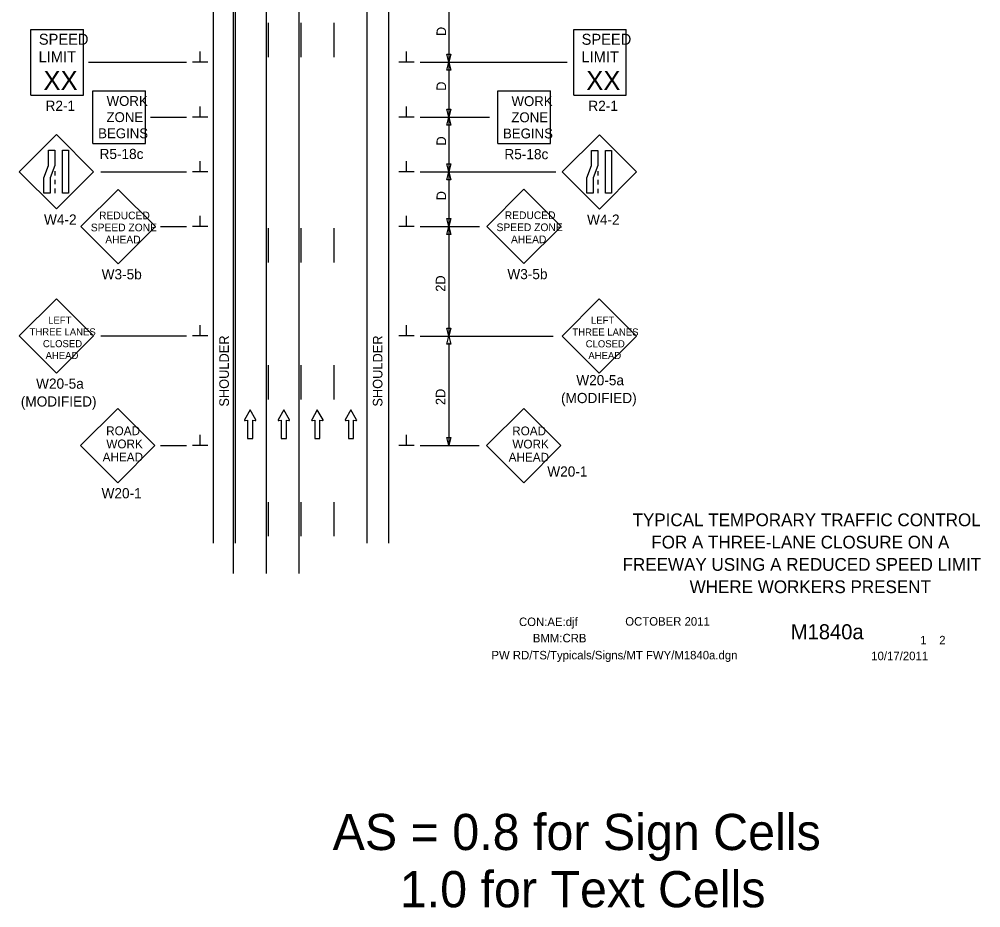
# Model space of a CAD drawing. Extents: x 16726 to 18475, y 5752 to 6929.
# Drawn here: x 16726 to 17428, y 5752 to 6401 of the extents above; entities that cross this region are included whole.
import ezdxf

# ---------------------------------------------------------------- set-up
doc = ezdxf.new("R2010")
doc.units = 0
for name, color, linetype in [('ALI_LEGAL_EX', 7, 'Continuous'), ('BORDER', 7, 'Continuous'), ('BORDER_SIGNAL_WO', 7, 'Continuous'), ('MT_SCRATCH_LEVEL_E', 7, 'Continuous'), ('PAVT_EDGE_EX', 7, 'Continuous'), ('TRAFFIC_SIGNS_PR', 7, 'Continuous'), ('TYPICAL_TEXT_DIMEN_PR', 7, 'Continuous')]:
    doc.layers.add(name, color=color, linetype=linetype)

msp = doc.modelspace()

# ---------------------------------------------------------------- linework, layer by layer
at = {"layer": 'ALI_LEGAL_EX'}
for p, q in [((16881.97, 6876.43), (16881.97, 5996.39)), ((16905.97, 6876.43), (16905.97, 5996.39)), ((16929.97, 6876.43), (16929.97, 5996.39))]:
    msp.add_line(p, q, dxfattribs=at)
for points in [[(16907.45, 6398.64), (16907.45, 6373.64)], [(16931.45, 6398.64), (16931.45, 6373.64)], [(16955.45, 6398.64), (16955.45, 6373.64)], [(16907.45, 6248.64), (16907.45, 6223.64)], [(16931.45, 6248.64), (16931.45, 6223.64)], [(16955.45, 6248.64), (16955.45, 6223.64)], [(16907.45, 6148.64), (16907.45, 6123.64)], [(16931.45, 6148.64), (16931.45, 6123.64)], [(16955.45, 6148.64), (16955.45, 6123.64)], [(16907.45, 6048.64), (16907.45, 6023.64)], [(16931.45, 6048.64), (16931.45, 6023.64)], [(16955.45, 6048.64), (16955.45, 6023.64)]]:
    msp.add_lwpolyline(points, dxfattribs=at)
at = {"layer": 'MT_SCRATCH_LEVEL_E'}
for p, q in [((16894.36, 6116.04), (16890.25, 6108.8)), ((16898.5, 6108.8), (16894.36, 6116.04)), ((16918.89, 6116.04), (16914.77, 6108.8)), ((16923.03, 6108.8), (16918.89, 6116.04)), ((16943.41, 6116.04), (16939.3, 6108.8)), ((16947.56, 6108.8), (16943.41, 6116.04)), ((16967.97, 6116.04), (16963.86, 6108.8)), ((16972.12, 6108.8), (16967.97, 6116.04)), ((16890.73, 6108.12), (16892.5, 6108.43)), ((16892.5, 6108.43), (16892.5, 6095.18)), ((16896.25, 6095.18), (16896.25, 6108.43)), ((16896.25, 6108.43), (16898.02, 6108.12)), ((16915.26, 6108.12), (16917.03, 6108.43)), ((16917.03, 6108.43), (16917.03, 6095.18)), ((16920.78, 6095.18), (16920.78, 6108.43)), ((16920.78, 6108.43), (16922.55, 6108.12)), ((16939.79, 6108.12), (16941.56, 6108.43)), ((16941.56, 6108.43), (16941.56, 6095.18)), ((16945.3, 6095.18), (16945.3, 6108.43)), ((16945.3, 6108.43), (16947.08, 6108.12)), ((16964.34, 6108.12), (16966.12, 6108.43)), ((16966.12, 6108.43), (16966.12, 6095.18)), ((16969.86, 6095.18), (16969.86, 6108.43)), ((16969.86, 6108.43), (16971.64, 6108.12)), ((16892.5, 6095.18), (16896.25, 6095.18)), ((16917.03, 6095.18), (16920.78, 6095.18)), ((16941.56, 6095.18), (16945.3, 6095.18)), ((16966.12, 6095.18), (16969.86, 6095.18))]:
    msp.add_line(p, q, dxfattribs=at)
for centre, start, end in [((16890.65, 6108.58), 150.42484, 279.96381), ((16898.09, 6108.58), 260.03619, 29.77312), ((16915.18, 6108.58), 150.42484, 279.96381), ((16922.62, 6108.58), 260.03619, 29.77312), ((16939.71, 6108.58), 150.42484, 279.96381), ((16947.15, 6108.58), 260.03619, 29.77312), ((16964.27, 6108.58), 150.42484, 279.96381), ((16971.71, 6108.58), 260.03619, 29.77312)]:
    msp.add_arc(centre, 0.463, start, end, dxfattribs=at)
at = {"layer": 'PAVT_EDGE_EX'}
for p, q in [((16867.45, 6928.88), (16867.45, 6018.6)), ((16883.45, 6928.88), (16883.45, 6018.6)), ((16979.45, 6928.88), (16979.45, 6018.6)), ((16995.45, 6928.88), (16995.45, 6018.6))]:
    msp.add_line(p, q, dxfattribs=at)
at = {"layer": 'TRAFFIC_SIGNS_PR'}
for p, q in [((16734.26, 6393.85), (16772.66, 6393.85)), ((16734.26, 6345.85), (16734.26, 6393.85)), ((16772.66, 6345.85), (16772.66, 6393.85)), ((17130.66, 6393.81), (17169.06, 6393.81)), ((17130.66, 6345.81), (17130.66, 6393.81)), ((17169.06, 6345.81), (17169.06, 6393.81)), ((16779.55, 6310.65), (16779.55, 6349.05)), ((16779.55, 6349.05), (16817.95, 6349.05)), ((16817.95, 6310.65), (16817.95, 6349.05)), ((17075.22, 6310.52), (17075.22, 6348.92)), ((17075.22, 6348.92), (17113.62, 6348.92)), ((17113.62, 6310.52), (17113.62, 6348.92)), ((16734.26, 6345.85), (16772.66, 6345.85)), ((17130.66, 6345.81), (17169.06, 6345.81)), ((16752.87, 6317.04), (16725.71, 6289.89)), ((16780.02, 6289.89), (16752.87, 6317.04)), ((17149.41, 6316.97), (17122.26, 6289.82)), ((17176.56, 6289.82), (17149.41, 6316.97)), ((16779.55, 6310.65), (16817.95, 6310.65)), ((17075.22, 6310.52), (17113.62, 6310.52)), ((16725.71, 6289.89), (16752.87, 6262.74)), ((16751.62, 6290.38), (16751.62, 6287.18)), ((16752.87, 6262.74), (16780.02, 6289.89)), ((17122.26, 6289.82), (17149.41, 6262.67)), ((17148.16, 6290.31), (17148.16, 6287.11)), ((17149.41, 6262.67), (17176.56, 6289.82)), ((16751.62, 6283.98), (16751.62, 6280.78)), ((17148.16, 6283.91), (17148.16, 6280.71)), ((16751.62, 6277.58), (16751.62, 6274.38)), ((16797.96, 6277.05), (16770.81, 6249.9)), ((16825.11, 6249.9), (16797.96, 6277.05)), ((17094.25, 6277.2), (17067.09, 6250.05)), ((17121.4, 6250.05), (17094.25, 6277.2)), ((17148.16, 6277.51), (17148.16, 6274.31)), ((16770.81, 6249.9), (16797.96, 6222.75)), ((16797.96, 6222.75), (16825.11, 6249.9)), ((17067.09, 6250.05), (17094.25, 6222.89)), ((17094.25, 6222.89), (17121.4, 6250.05)), ((16752.89, 6197.18), (16725.74, 6170.02)), ((16780.05, 6170.02), (16752.89, 6197.18)), ((17149.27, 6197.06), (17122.12, 6169.9)), ((17176.43, 6169.9), (17149.27, 6197.06)), ((16725.74, 6170.02), (16752.89, 6142.87)), ((16752.89, 6142.87), (16780.05, 6170.02)), ((17122.12, 6169.9), (17149.27, 6142.75)), ((17149.27, 6142.75), (17176.43, 6169.9)), ((16797.67, 6117.1), (16770.51, 6089.95)), ((16824.82, 6089.95), (16797.67, 6117.1)), ((17094.19, 6117.02), (17067.03, 6089.87)), ((17121.34, 6089.87), (17094.19, 6117.02)), ((16770.51, 6089.95), (16797.67, 6062.8)), ((16797.67, 6062.8), (16824.82, 6089.95)), ((17067.03, 6089.87), (17094.19, 6062.72)), ((17094.19, 6062.72), (17121.34, 6089.87))]:
    msp.add_line(p, q, dxfattribs=at)
for points in [[(16751.62, 6305.63), (16751.62, 6294.45), (16748.28, 6285.56), (16748.28, 6274.38), (16743.78, 6274.38), (16743.78, 6285.56), (16747.13, 6294.45), (16747.13, 6305.63)], [(16761.76, 6305.63), (16761.76, 6274.38), (16757.26, 6274.38), (16757.26, 6305.63)], [(17148.16, 6305.56), (17148.16, 6294.38), (17144.82, 6285.49), (17144.82, 6274.31), (17140.33, 6274.31), (17140.33, 6285.49), (17143.67, 6294.38), (17143.67, 6305.56)], [(17158.3, 6305.56), (17158.3, 6274.31), (17153.81, 6274.31), (17153.81, 6305.56)]]:
    msp.add_lwpolyline(points, close=True, dxfattribs=at)
at = {"layer": 'TYPICAL_TEXT_DIMEN_PR'}
for p, q in [((17039.45, 6409.9), (17039.45, 6369.9)), ((16857.82, 6369.9), (16857.82, 6377.69)), ((17008.57, 6369.9), (17008.57, 6377.69)), ((16776.42, 6369.9), (16847.86, 6369.9)), ((16863.45, 6369.9), (16852.2, 6369.9)), ((17014.2, 6369.9), (17002.95, 6369.9)), ((17018.45, 6369.9), (17125.77, 6369.9)), ((17039.45, 6369.9), (17037.88, 6375.76)), ((17037.88, 6375.76), (17039.45, 6375.76)), ((17037.88, 6364.04), (17039.45, 6369.9)), ((17039.45, 6375.76), (17041.02, 6375.76)), ((17041.02, 6375.76), (17039.45, 6369.9)), ((17039.45, 6369.9), (17039.45, 6329.9)), ((17039.45, 6369.9), (17041.02, 6364.04)), ((17039.45, 6364.04), (17037.88, 6364.04)), ((17041.02, 6364.04), (17039.45, 6364.04)), ((16857.82, 6329.9), (16857.82, 6337.69)), ((17008.57, 6329.9), (17008.57, 6337.69)), ((17039.45, 6329.9), (17037.88, 6335.76)), ((17037.88, 6335.76), (17039.45, 6335.76)), ((17039.45, 6335.76), (17041.02, 6335.76)), ((17041.02, 6335.76), (17039.45, 6329.9)), ((16821.47, 6329.9), (16847.86, 6329.9)), ((16863.45, 6329.9), (16852.2, 6329.9)), ((17014.2, 6329.9), (17002.95, 6329.9)), ((17018.45, 6329.9), (17069.12, 6329.9)), ((17037.88, 6324.04), (17039.45, 6329.9)), ((17039.45, 6329.9), (17039.45, 6289.9)), ((17039.45, 6329.9), (17041.02, 6324.04)), ((17039.45, 6324.04), (17037.88, 6324.04)), ((17041.02, 6324.04), (17039.45, 6324.04)), ((16857.82, 6289.9), (16857.82, 6297.69)), ((17008.57, 6289.9), (17008.57, 6297.69)), ((17039.45, 6289.9), (17037.88, 6295.76)), ((17037.88, 6295.76), (17039.45, 6295.76)), ((17039.45, 6295.76), (17041.02, 6295.76)), ((17041.02, 6295.76), (17039.45, 6289.9)), ((16785.34, 6289.9), (16847.86, 6289.9)), ((16863.45, 6289.9), (16852.2, 6289.9)), ((17014.2, 6289.9), (17002.95, 6289.9)), ((17018.45, 6289.9), (17117.62, 6289.9)), ((17037.88, 6284.04), (17039.45, 6289.9)), ((17039.45, 6289.9), (17039.45, 6249.9)), ((17039.45, 6289.9), (17041.02, 6284.04)), ((17039.45, 6284.04), (17037.88, 6284.04)), ((17041.02, 6284.04), (17039.45, 6284.04)), ((16857.82, 6249.9), (16857.82, 6257.69)), ((17008.57, 6249.9), (17008.57, 6257.69)), ((16828.77, 6249.9), (16847.86, 6249.9)), ((16863.45, 6249.9), (16852.2, 6249.9)), ((17014.2, 6249.9), (17002.95, 6249.9)), ((17018.45, 6249.9), (17061.81, 6249.9)), ((17039.45, 6249.9), (17037.88, 6255.76)), ((17037.88, 6255.76), (17039.45, 6255.76)), ((17037.88, 6244.04), (17039.45, 6249.9)), ((17039.45, 6255.76), (17041.02, 6255.76)), ((17041.02, 6255.76), (17039.45, 6249.9)), ((17039.45, 6249.9), (17039.45, 6169.9)), ((17039.45, 6249.9), (17041.02, 6244.04)), ((17039.45, 6244.04), (17037.88, 6244.04)), ((17041.02, 6244.04), (17039.45, 6244.04)), ((16857.82, 6170.02), (16857.82, 6177.81)), ((17008.57, 6170.02), (17008.57, 6177.81)), ((17039.45, 6169.9), (17037.88, 6175.77)), ((17037.88, 6175.77), (17039.45, 6175.77)), ((17039.45, 6175.77), (17041.02, 6175.77)), ((17041.02, 6175.77), (17039.45, 6169.9)), ((16785.24, 6170.02), (16847.86, 6170.02)), ((16863.45, 6170.02), (16852.2, 6170.02)), ((17014.2, 6170.02), (17002.95, 6170.02)), ((17018.45, 6169.9), (17115.67, 6169.9)), ((17037.88, 6164.04), (17039.45, 6169.9)), ((17039.45, 6169.9), (17041.02, 6164.04)), ((17039.45, 6164.04), (17037.88, 6164.04)), ((17039.45, 6164.9), (17039.45, 6089.9)), ((17041.02, 6164.04), (17039.45, 6164.04)), ((16857.82, 6089.95), (16857.82, 6097.74)), ((17008.57, 6089.95), (17008.57, 6097.74)), ((17039.45, 6089.9), (17037.88, 6095.77)), ((17037.88, 6095.77), (17039.45, 6095.77)), ((17039.45, 6095.77), (17041.02, 6095.77)), ((17041.02, 6095.77), (17039.45, 6089.9)), ((16828.77, 6089.95), (16847.86, 6089.95)), ((16863.45, 6089.95), (16852.2, 6089.95)), ((17014.2, 6089.95), (17002.95, 6089.95)), ((17018.45, 6089.9), (17061.49, 6089.9))]:
    msp.add_line(p, q, dxfattribs=at)

# ---------------------------------------------------------------- texts
at = {"layer": 'BORDER'}
for s, p in [('TYPICAL TEMPORARY TRAFFIC CONTROL', (17173.6, 6031.02)), ('FOR A THREE-LANE CLOSURE ON A', (17187.3, 6014.72)), ('FREEWAY USING A REDUCED SPEED LIMIT', (17166.3, 5998.42)), ('WHERE WORKERS PRESENT', (17215.3, 5982.12))]:
    msp.add_text(s, height=9.3, dxfattribs=at).set_placement(p)
at = {"layer": 'BORDER_SIGNAL_WO'}
for s, height, p in [('CON:AE:djf  ', 6.2, (17090.69, 5958.06)), ('    OCTOBER 2011', 6.2, (17159.08, 5958.34)), ('    M1840a   ', 11, (17272.86, 5948.38)), ('BMM:CRB', 6.2, (17100.81, 5946.17)), (' 1    2 ', 6.2, (17381.45, 5944.7)), ('PW RD/TS/Typicals/Signs/MT FWY/M1840a.dgn      ', 6.2, (17070.55, 5933.71)), ('10/17/2011', 6.2, (17347.93, 5933.13)), ('AS = 0.8 for Sign Cells', 26.4241, (16954.57, 5794.42)), ('     1.0 for Text Cells', 26.4241, (16954.57, 5752.64))]:
    msp.add_text(s, height=height, dxfattribs=at).set_placement(p)
at = {"layer": 'TRAFFIC_SIGNS_PR'}
for s, height, p in [('SPEED', 8, (16740.03, 6382.72)), ('SPEED', 8, (17136.43, 6382.68)), ('LIMIT', 8, (16739.87, 6369.92)), ('LIMIT', 8, (17136.27, 6369.88)), ('XX', 14.031, (16743.38, 6349.61)), ('XX', 14.031, (17139.77, 6349.57)), ('R2-1', 7.44, (16744.94, 6334.42)), ('WORK', 7.217, (16789.54, 6338.02)), ('WORK', 7.217, (17085.22, 6337.89)), ('R2-1', 7.44, (17141.34, 6334.37)), ('ZONE', 7.217, (16789.43, 6326.21)), ('ZONE', 7.217, (17085.1, 6326.08)), ('BEGINS', 7.217, (16783.35, 6314.4)), ('BEGINS', 7.217, (17079.02, 6314.27)), ('R5-18c', 7.44, (16784.36, 6299.21)), ('R5-18c', 7.44, (17080.03, 6299.08)), ('W4-2', 7.44, (16743.82, 6251.3)), ('REDUCED', 5.6, (16784.02, 6255.21)), ('REDUCED', 5.6, (17080.3, 6255.35)), ('W4-2', 7.44, (17140.37, 6251.23)), ('SPEED ZONE', 5.6, (16778.01, 6246.41)), ('SPEED ZONE', 5.6, (17074.3, 6246.55)), ('AHEAD', 5.6, (16788.57, 6237.61)), ('AHEAD', 5.6, (17084.86, 6237.75)), ('W3-5b', 7.44, (16785.91, 6211.31)), ('W3-5b', 7.44, (17082.2, 6211.45)), ('LEFT', 5.2, (16746.84, 6178.96)), ('LEFT', 5.2, (17143.22, 6178.84)), ('THREE LANES', 5.2, (16733.28, 6170.36)), ('THREE LANES', 5.2, (17129.66, 6170.24)), ('CLOSED', 5.2, (16743.01, 6161.76)), ('CLOSED', 5.2, (17139.39, 6161.64)), ('AHEAD', 5.2, (16744.96, 6153.16)), ('AHEAD', 5.2, (17141.34, 6153.04)), ('W20-5a', 7.44, (16738.03, 6131.43)), ('W20-5a', 7.44, (17132.53, 6133.96)), ('(MODIFIED)', 7.44, (16726.89, 6118.39)), ('(MODIFIED)', 7.44, (17121.38, 6120.92)), ('ROAD', 6.4, (16789.21, 6097.49)), ('ROAD', 6.4, (17085.73, 6097.4)), ('WORK', 6.4, (16789.32, 6087.89)), ('WORK', 6.4, (17085.84, 6087.8)), ('AHEAD', 6.4, (16786.63, 6078.29)), ('AHEAD', 6.4, (17083.15, 6078.2)), ('W20-1', 7.44, (17111.36, 6067.23)), ('W20-1', 7.44, (16785.84, 6051.36))]:
    msp.add_text(s, height=height, dxfattribs=at).set_placement(p)
at = {"layer": 'TYPICAL_TEXT_DIMEN_PR'}
for s, p in [('D', (17037.43, 6389.04)), ('D', (17037.43, 6349.04)), ('D', (17037.43, 6309.04)), ('D', (17037.43, 6269.04)), ('2D', (17036.89, 6202.25)), ('SHOULDER', (16878.82, 6118.34)), ('SHOULDER', (16990.96, 6118.34)), ('2D', (17036.89, 6119.47))]:
    msp.add_text(s, height=7, rotation=90, dxfattribs=at).set_placement(p)

doc.saveas('drawing.dxf')
